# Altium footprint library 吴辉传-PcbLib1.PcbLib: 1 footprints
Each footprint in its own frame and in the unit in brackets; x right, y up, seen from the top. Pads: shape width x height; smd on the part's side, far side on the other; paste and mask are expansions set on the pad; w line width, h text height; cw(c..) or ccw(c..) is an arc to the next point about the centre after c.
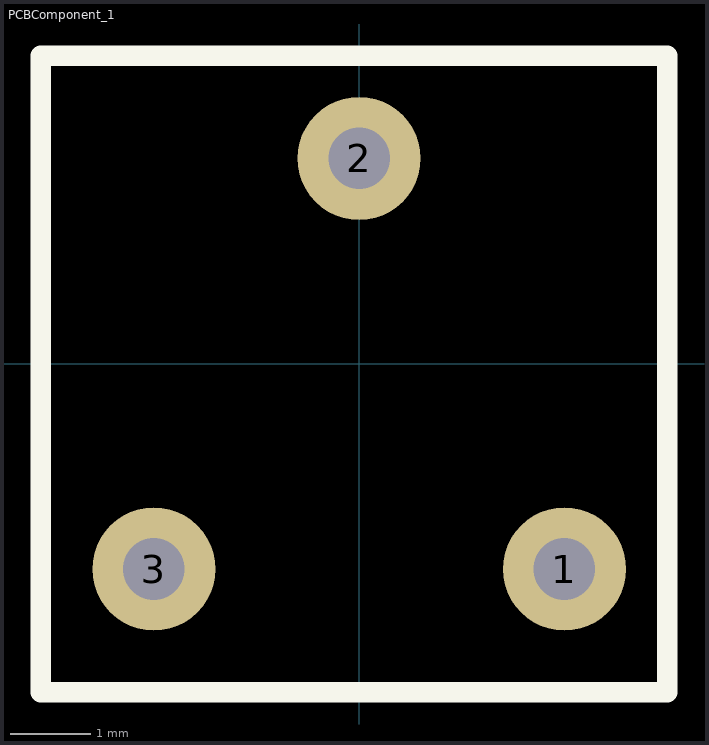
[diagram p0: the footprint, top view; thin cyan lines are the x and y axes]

## PCBComponent_1 [mil]
pads (3):
  round 60 hole 30: 1(100,-100) 2(0,100) 3(-100,-100)
Top Overlay:
  lines w10: -155,-160 150,-160 150,150 -155,150 -155,-160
